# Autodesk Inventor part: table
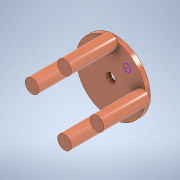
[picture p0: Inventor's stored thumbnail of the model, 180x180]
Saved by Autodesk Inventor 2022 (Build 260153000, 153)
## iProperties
Created: 2021-06
Part Number: table
Material: Wood (Walnut)
Document SubType Name: Modeling
Designer: adams
Density: 0.55 g/cm^3
Appearance: Walnut - Natural Polished
Author: adams
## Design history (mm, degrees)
sketch "Sketch1"
  geometry: 1 further point
sketch "Sketch2"
  geometry: C1 r 190.5 at (0, 0); 1 further point
  constraints: 1 centre point, 1 coincident
  dimensions: "d0" = 381 diameter of C1
extrude "Extrusion1" new body sketch "Sketch2" distance "d1" = 25.4; taper "d2" = 0 deg
sketch "Sketch3"
  geometry: C1 r 25.4 at (0, 0); 1 further point
  constraints: 1 centre point, 1 coincident
  dimensions: "d3" = 50.8 diameter of C1
extrude "Extrusion2" cut sketch "Sketch3" extent not by distance; stored distance "d4" = 0; taper "d5" = 0 deg
sketch "Sketch4"
  geometry: C1 r 38.1 at (0, 177.8); C2 r 38.1 at (-177.8, 0); C3 r 38.1 at (0, -177.8); C4 r 38.1 at (177.8, 0); 1 further point
  constraints: 4 centre point
  dimensions: "d6" = 76.2 diameter of C1; "d7" = 177.8 distance of C1.centre point (0, 0); "d8" = 76.2 diameter of C2; "d9" = 177.8 distance of C2.centre point (0, 0); "d10" = 76.2 diameter of C3; "d11" = 177.8 distance of C3.centre point (0, 0); "d12" = 76.2 diameter of C4; "d13" = 177.8 distance of point (0, 0) C4.centre
extrude "Extrusion3" join sketch "Sketch4" distance "d14" = 254; taper "d15" = 0 deg
sketch "Sketch5"
  geometry: C1 r 19.406 at (87.769, 92.18); 1 further point
  constraints: 1 centre point
body "Solid1"
